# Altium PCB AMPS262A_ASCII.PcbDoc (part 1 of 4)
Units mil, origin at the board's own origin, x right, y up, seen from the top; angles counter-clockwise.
Board outline 5314.96 x 4803.15 mil, 4 copper layers (Top Layer, GND, Copper Layer 3, Bottom Layer), stack 79.28 mil thick; 324 components, 156 nets, 943 pads, 1411 vias.
Unrouted connection lines stored in the file: 130.
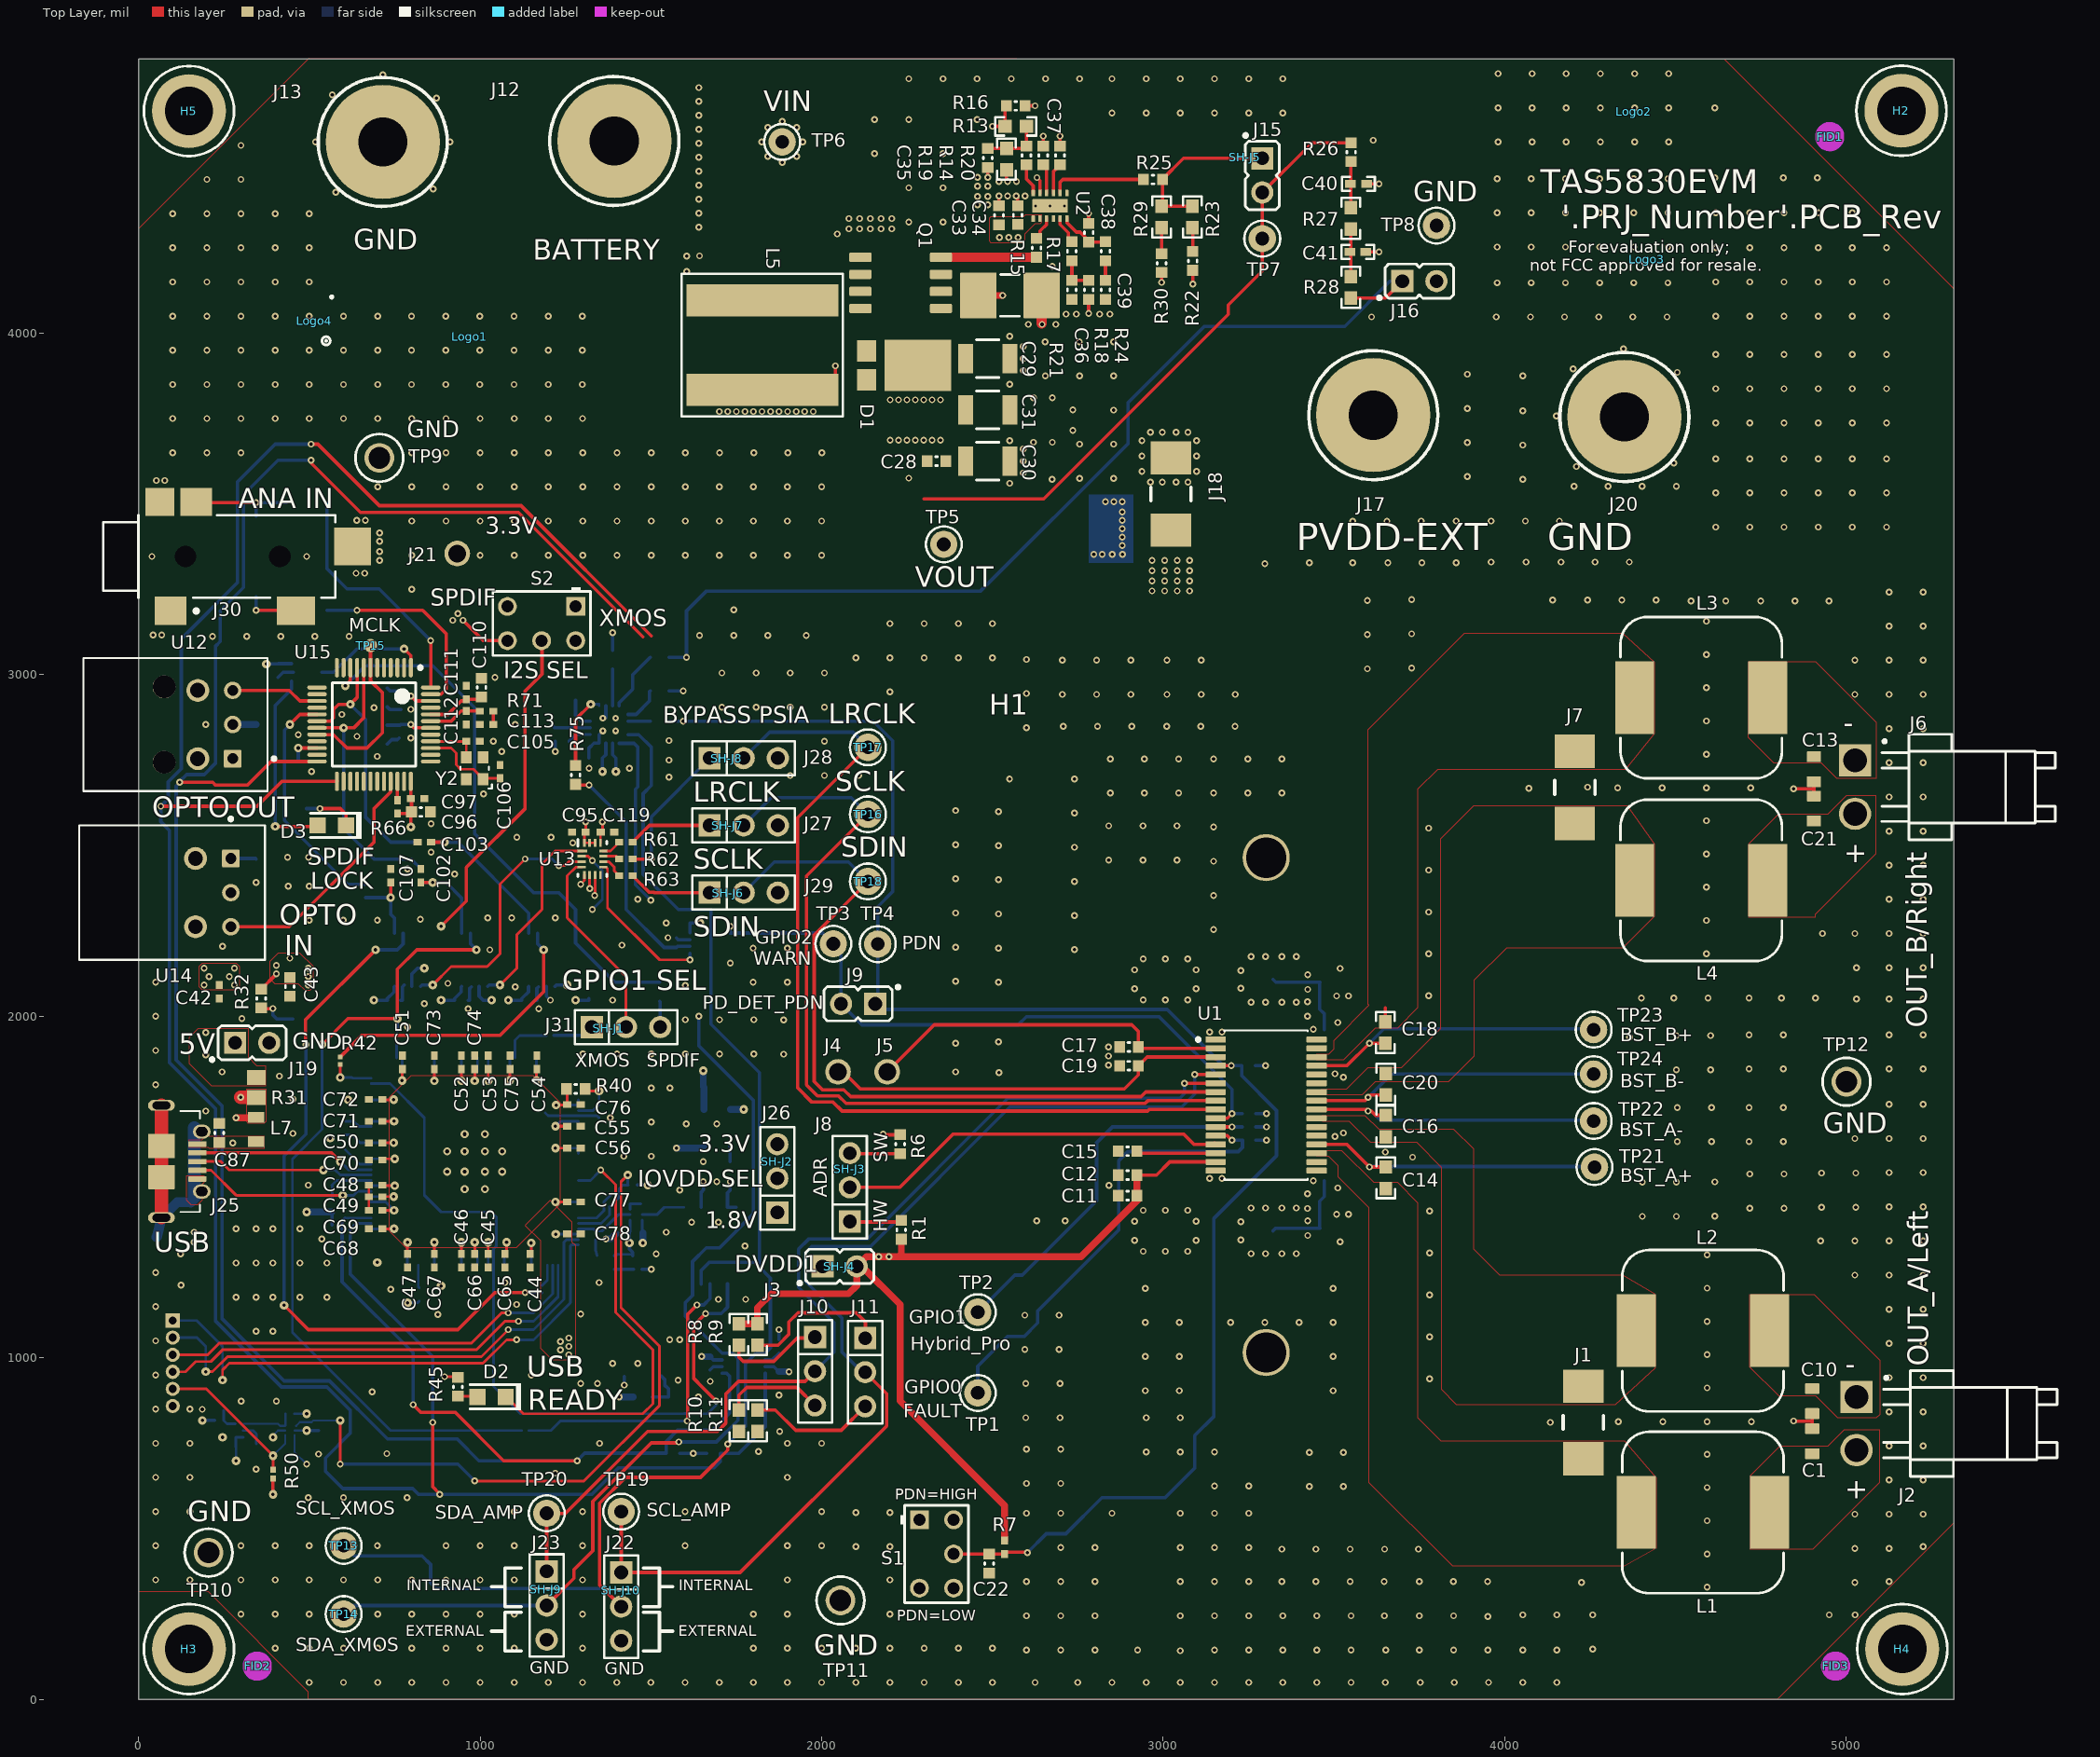
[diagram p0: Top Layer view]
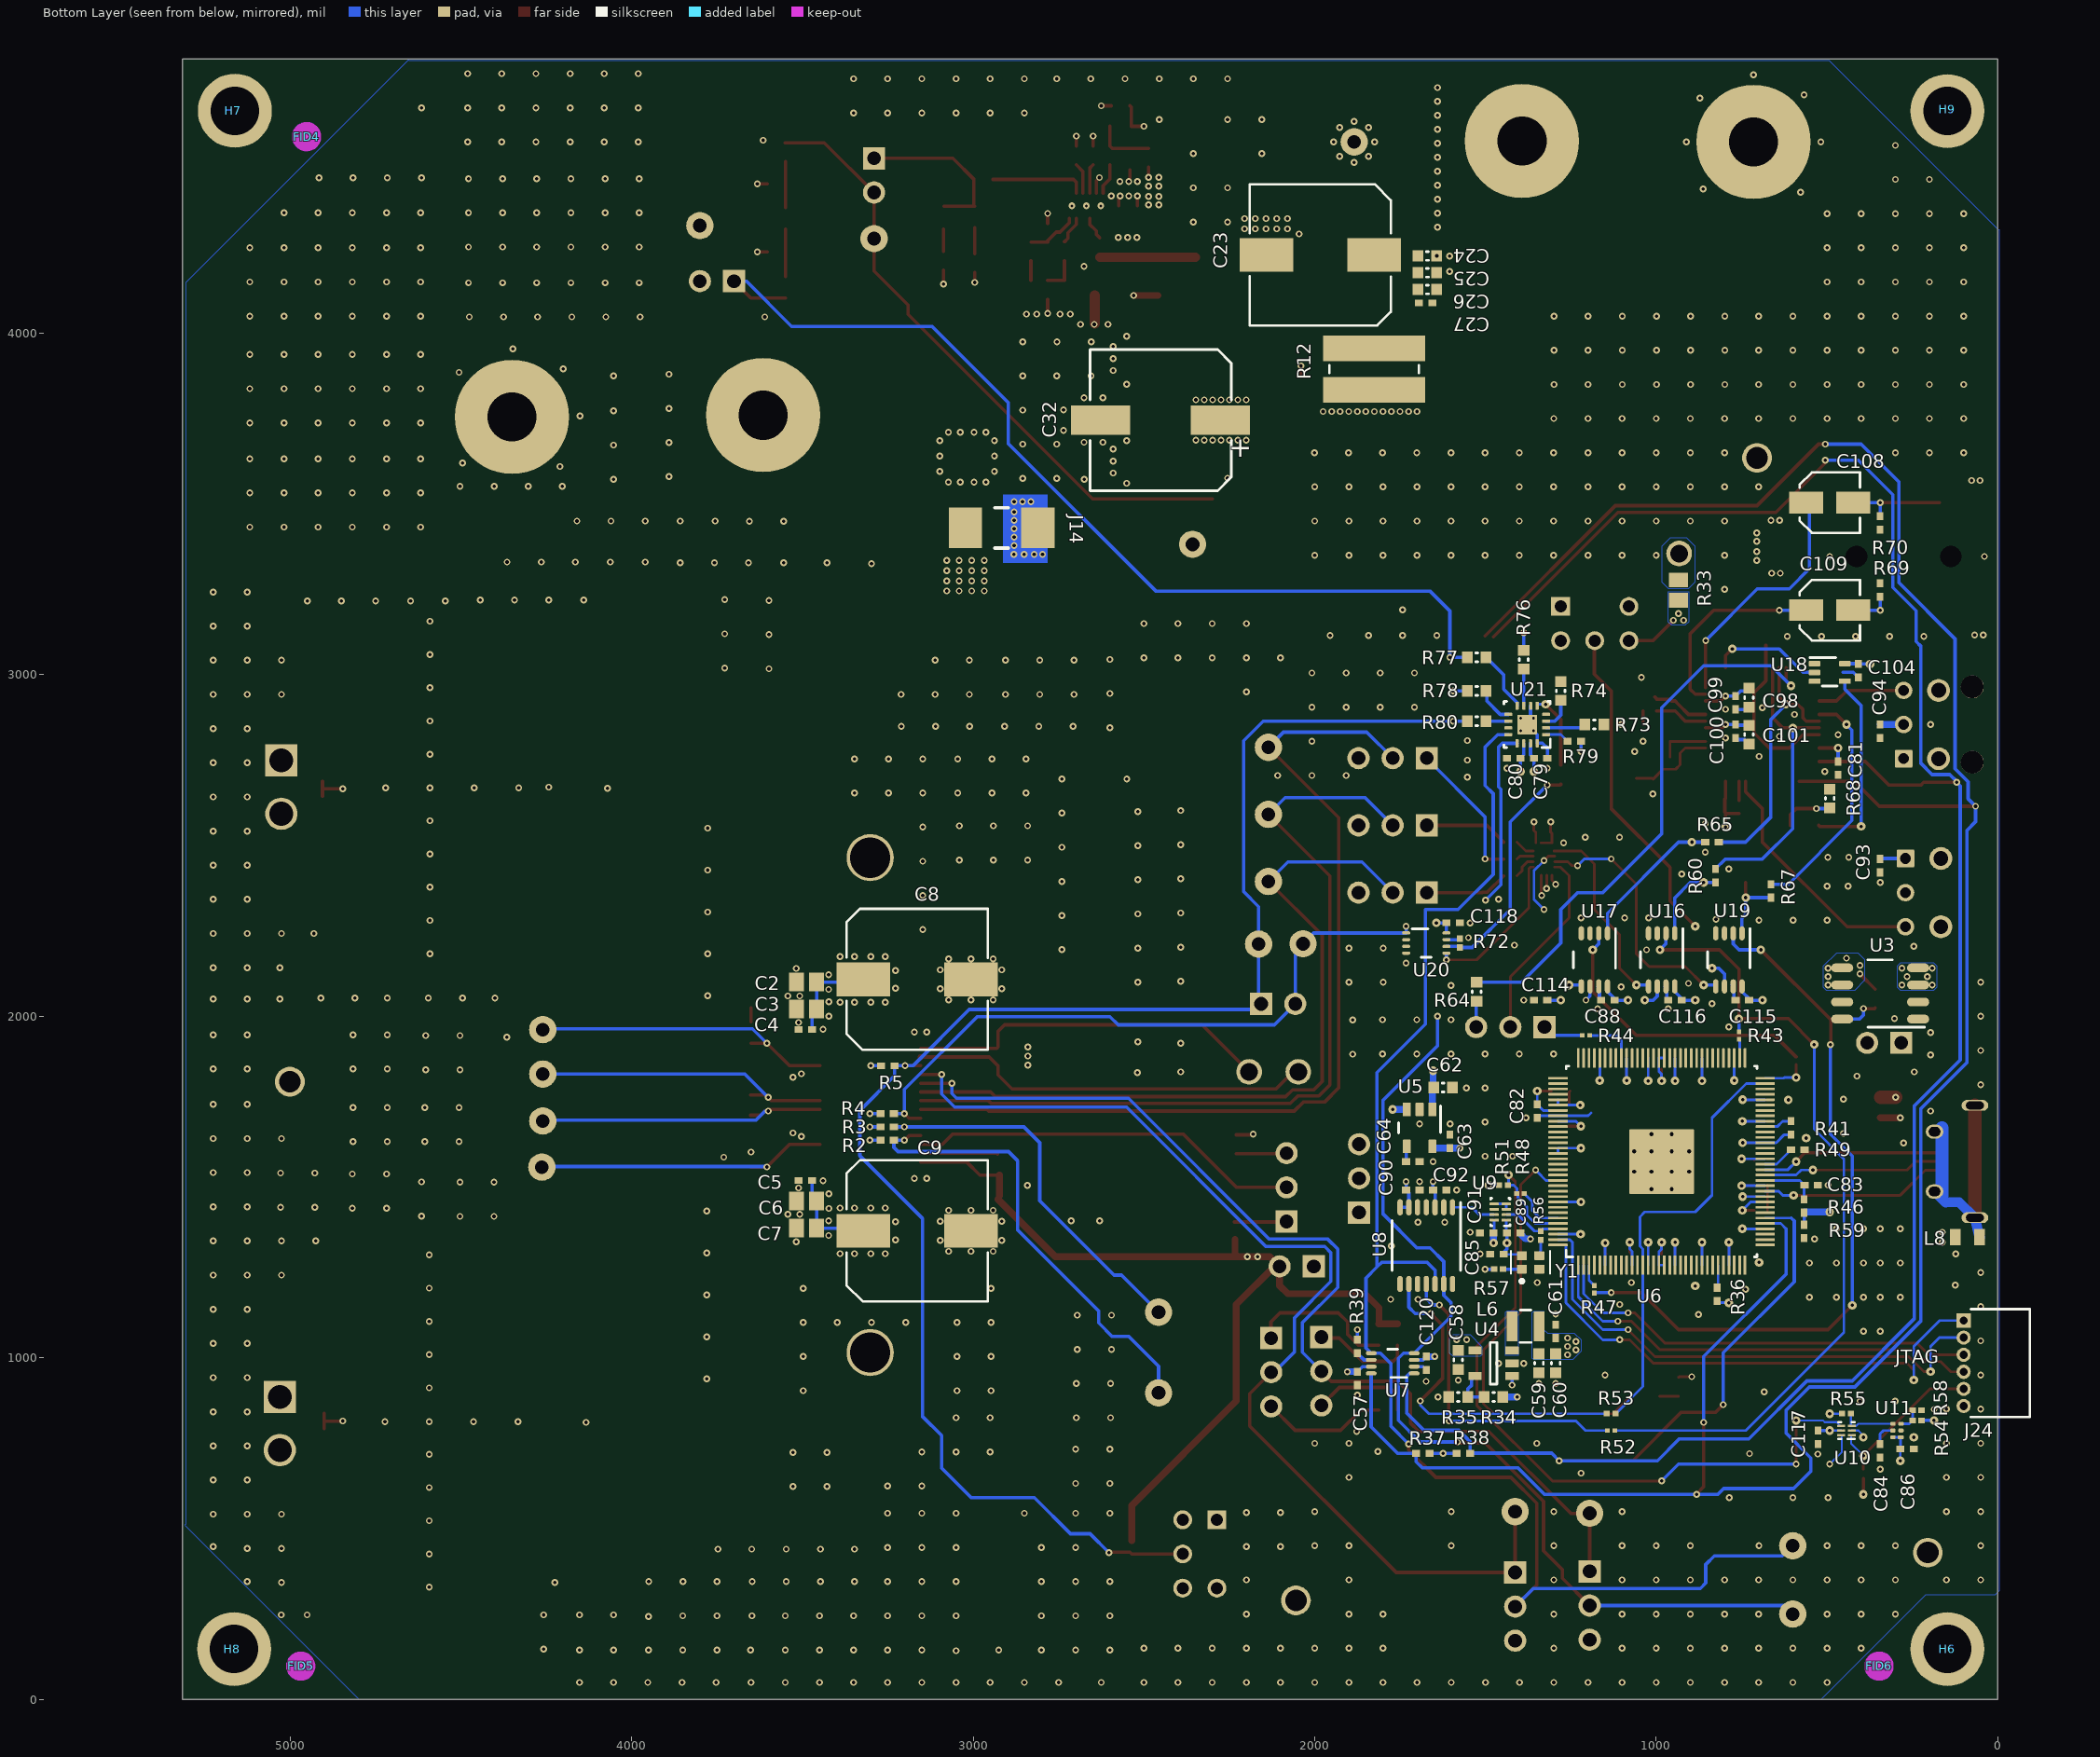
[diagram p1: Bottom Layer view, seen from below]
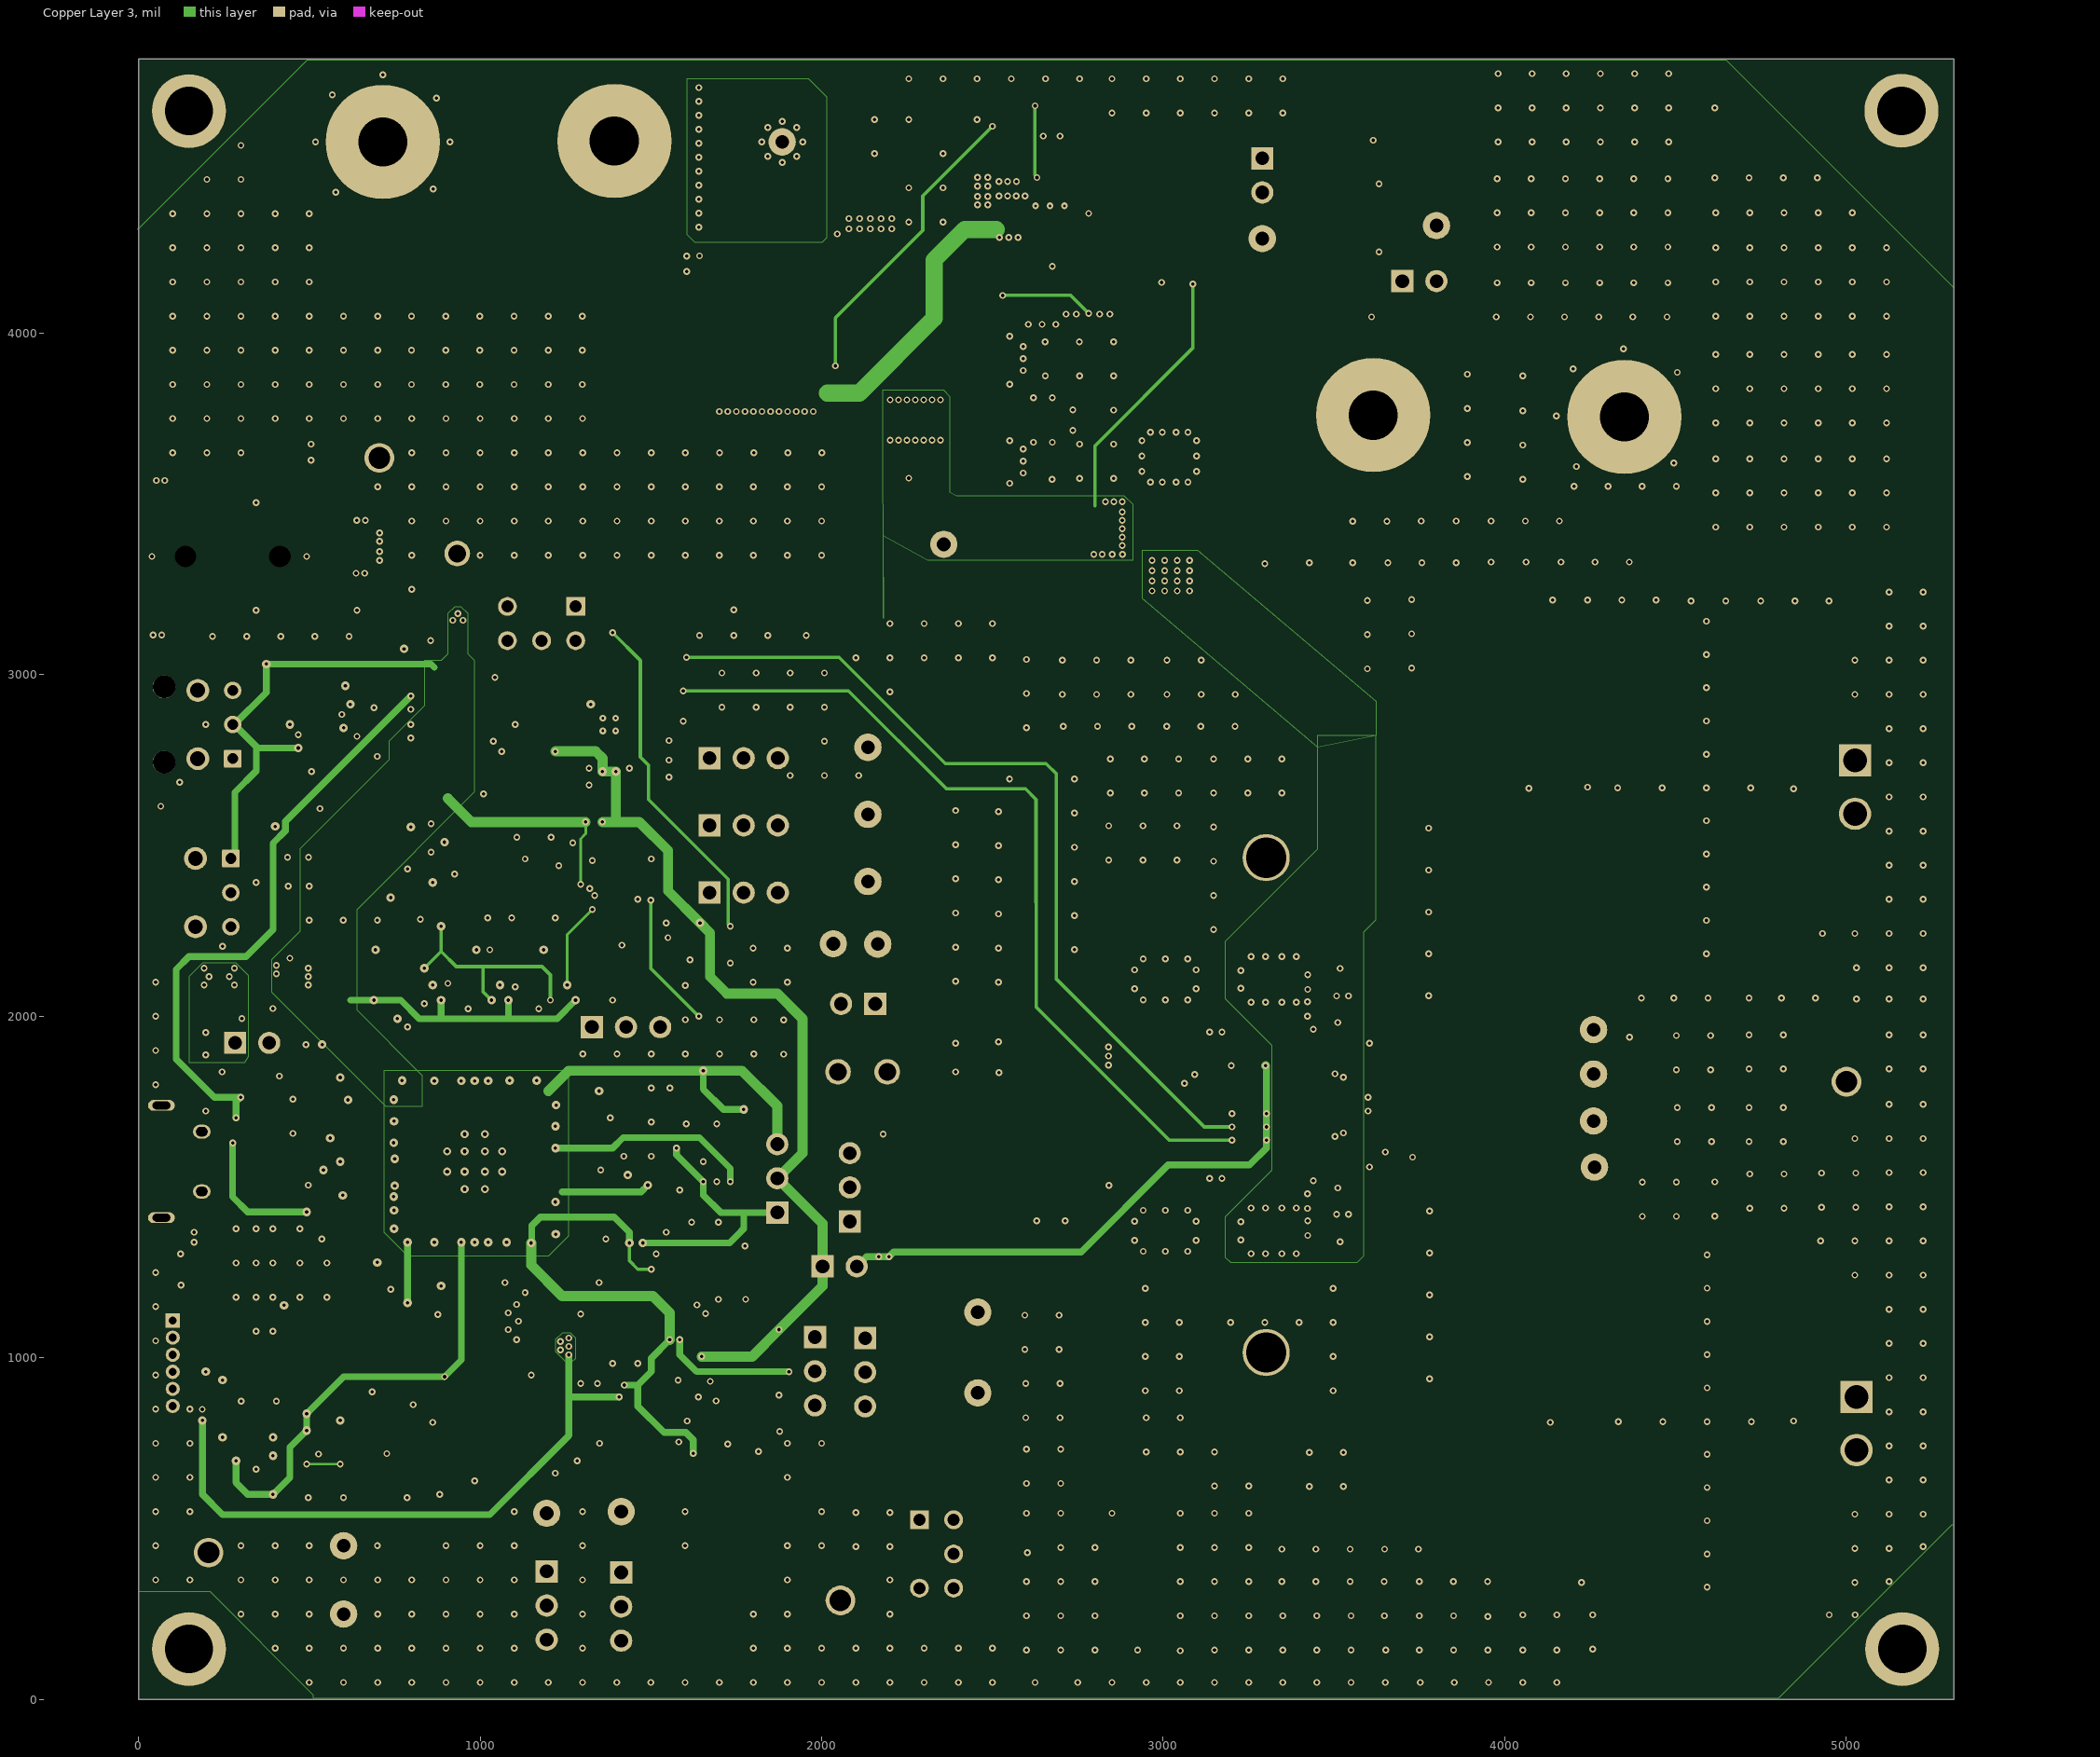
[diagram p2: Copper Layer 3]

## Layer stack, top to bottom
Top Solder: solder mask 0.4, Solder Resist, Dk 3.5
Top Layer: signal copper 2.74
Dielectric 1: prepreg 25, FR-4, Dk 4.2
GND: signal copper 1.4
Dielectric1: core 21, FR-4, Dk 4.2
Copper Layer 3: signal copper 1.4
Dielectric 3: prepreg 25, FR-4, Dk 4.2
Bottom Layer: signal copper 2.74
Bottom Solder: solder mask 0.4, Solder Resist, Dk 3.5

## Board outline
0,0 0,4803.15 5314.96,4803.15 5314.96,0

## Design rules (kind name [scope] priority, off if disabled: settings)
AcuteAngle [All] p0: scope1count=1 scope1_0_kind=Board scope1_0_value=Board scope2count=1 scope2_0_kind=Board scope2_0_value=Board commentlength=0 minimum=4.50000000000000E+0001
AcuteAngle [All] p1: minimum=4.50000000000000E+0001 checktracksonly=FALSE
AssemblyTestPointUsage [All] p0: scope1count=1 scope1_0_kind=Board scope1_0_value=Board scope2count=1 scope2_0_kind=Board scope2_0_value=Board commentlength=0
AssemblyTestPointUsage [All] p1: valid=2
AssemblyTestpoint [All] p0: scope1count=1 scope1_0_kind=Board scope1_0_value=Board scope2count=1 scope2_0_kind=Board scope2_0_value=Board commentlength=0
BoardOutlineClearance [All] p0 off: scope1count=1 scope1_0_kind=Board scope1_0_value=Board scope2count=1 scope2_0_kind=Board scope2_0_value=Board commentlength=172 gap=75 // Protel DXP Scope 1 Expression Was: OnCopper and Not InComponentClass('Logo') and not InComponentClass('FiducialMark') and not InRegion(1000,500,4000,800) and not InPoly
BoardOutlineClearance BoardOutlineClearance_CONN_USB_DX4R205JJA [All] p0 off: scope1count=1 scope1_0_kind=Board scope1_0_value=Board scope2count=1 scope2_0_kind=Board scope2_0_value=Board commentlength=254 gap=75 // Protel DXP Scope 1 Expression Was: (OnCopper AND (HasFootprint('CONN_USB_DX4R205JJA') OR HasFootprint('SWITCHCRAFT_35RASM'))) and Not InComponentClass('Logo') and not InComponentClass('FiducialMark') and not InRegion(1000,500,4000,800) and not InPoly
BoardOutlineClearance BoardOutlineClearance_Poly [All] p0 off: scope1count=1 scope1_0_kind=Board scope1_0_value=Board scope2count=1 scope2_0_kind=Board scope2_0_value=Board commentlength=58 gap=25 // Protel DXP Scope 1 Expression Was: OnCopper and IsPoly
BoardOutlineClearance BoardOutlineClearance_MountingHoles [All] p0 off: scope1count=1 scope1_0_kind=Board scope1_0_value=Board scope2count=1 scope2_0_kind=Board scope2_0_value=Board commentlength=86 gap=39.37 // Protel DXP Scope 1 Expression Was: OnCopper and InComponentClass('Mounting Holes')
BoardOutlineClearance BoardOutlineClearance_MountingHoles [OnCopper and InComponentClass('Mounting Holes')] p1: gap=39.37 ignorepadtopadclearanceinfootprint=FALSE
BoardOutlineClearance BoardOutlineClearance_Poly [OnCopper and IsPoly] p2: gap=25 ignorepadtopadclearanceinfootprint=FALSE
BoardOutlineClearance BoardOutlineClearance_CONN_USB_DX4R205JJA [(OnCopper AND (HasFootprint('CONN_USB_DX4R205JJA') OR HasFootprint('SWITCHCRAFT_35RASM'))) and Not InComponentClass('Logo') and not InComponentClass('FiducialMark') and not InRegion(1000,500,4000,800) and not InPoly] p3: gap=75 ignorepadtopadclearanceinfootprint=FALSE except(15: SMDPad-OutlineEdge THPad-OutlineEdge; 29: Via-OutlineEdge)
BoardOutlineClearance [OnCopper and Not InComponentClass('Logo') and not InComponentClass('FiducialMark') and not InRegion(1000,500,4000,800) and not InPoly] p4: gap=75 ignorepadtopadclearanceinfootprint=FALSE except(20: Track-OutlineEdge; 25: Poly-OutlineEdge Poly-CavityEdge Poly-CutoutEdge Poly-SplitBarrior Poly-SplitContinuation Region-OutlineEdge Region-CavityEdge Region-CutoutEdge Region-SplitBarrior Region-SplitContinuation; 29: Via-OutlineEdge; 35: SMDPad-OutlineEdge; 39.37: THPad-OutlineEdge)
Clearance "FootPrint Lib Error" [All] p0: scope1count=1 scope1_0_kind=Footprint scope1_0_value=DSF* scope2count=1 scope2_0_kind=Board scope2_0_value=Board commentlength=0 gap=7
Clearance [All] p0: scope1count=1 scope1_0_kind=Board scope1_0_value=Board scope2count=1 scope2_0_kind=Board scope2_0_value=Board commentlength=0 gap=7.87
Clearance Clearance_FiducialMark [All] p0 off: scope1count=1 scope1_0_kind=Board scope1_0_value=Board scope2count=1 scope2_0_kind=Board scope2_0_value=Board commentlength=81 gap=0 // Protel DXP Scope 2 Expression Was: IsPad and InComponentClass('FiducialMark')
Clearance Clearance_Poly [All] p0 off: scope1count=1 scope1_0_kind=Board scope1_0_value=Board scope2count=1 scope2_0_kind=Board scope2_0_value=Board commentlength=48 gap=7.87 // Protel DXP Scope 1 Expression Was: InPolygon
Clearance Clearance_Keepouts [All] p0 off: scope1count=1 scope1_0_kind=Board scope1_0_value=Board scope2count=1 scope2_0_kind=Board scope2_0_value=Board commentlength=99 gap=0 // Protel DXP Scope 2 Expression Was: ((IsTrack Or IsArc) And Not InPoly) And IsFree and IsKeepOut
Clearance Clearance_FiducialMark [IsKeepOut and InComponentClass('FiducialMark') vs IsPad and InComponentClass('FiducialMark')] p1: gap=0 ignorepadtopadclearanceinfootprint=FALSE
Clearance Clearance_Keepouts [((IsTrack Or IsArc) And Not InPoly) And IsFree and IsKeepOut vs ((IsTrack Or IsArc) And Not InPoly) And IsFree and IsKeepOut] p2: gap=0 ignorepadtopadclearanceinfootprint=FALSE
Clearance Clearance_Poly [InPolygon] p3: gap=7.87 ignorepadtopadclearanceinfootprint=TRUE
Clearance "FootPrint Lib Error" [HasFootprint('DSF*')] p4: gap=7 ignorepadtopadclearanceinfootprint=TRUE except(0: Arc-Hole Track-Hole SMDPad-Hole THPad-Hole Via-Hole Fill-Hole Poly-Hole Region-Hole Text-Hole)
Clearance [All] p5: gap=7.87 ignorepadtopadclearanceinfootprint=TRUE except(0: Arc-Hole Track-Hole SMDPad-Hole THPad-Hole Via-Hole Fill-Hole Poly-Hole Region-Hole Text-Hole)
ComponentClearance ComponentClearance_MOUNTINGHOLE [All] p0 off: scope1count=1 scope1_0_kind=Footprint scope1_0_value="APM_RM3X8MM 2701" scope2count=1 scope2_0_kind=Footprint scope2_0_value=Keystone_24434 commentlength=0 gap=0 collisioncheckmode=3
ComponentClearance ComponentClearance_HEATSINK [All] p0 off: scope1count=1 scope1_0_kind=Component scope1_0_value=H1 scope2count=1 scope2_0_kind=Component scope2_0_value=U1 commentlength=0 gap=0 collisioncheckmode=3
ComponentClearance [All] p0 off: scope1count=1 scope1_0_kind=Board scope1_0_value=Board scope2count=1 scope2_0_kind=Board scope2_0_value=Board commentlength=0 gap=0 collisioncheckmode=3
ComponentClearance ComponentClearance_THtoTH [All] p0 off: scope1count=1 scope1_0_kind=Board scope1_0_value=Board scope2count=1 scope2_0_kind=Board scope2_0_value=Board commentlength=54 gap=30 collisioncheckmode=3 // Protel DXP Scope 2 Expression Was: IsThruComponent
ComponentClearance ComponentClearance_THtoSMT [All] p0 off: scope1count=1 scope1_0_kind=Board scope1_0_value=Board scope2count=1 scope2_0_kind=Board scope2_0_value=Board commentlength=53 gap=25 collisioncheckmode=3 // Protel DXP Scope 2 Expression Was: IsSMTComponent
ComponentClearance ComponentClearance_SmallPassives [All] p0 off: scope1count=1 scope1_0_kind=Board scope1_0_value=Board scope2count=1 scope2_0_kind=Board scope2_0_value=Board commentlength=1054 gap=8.5 collisioncheckmode=3 // Protel DXP Scope 2 Expression Was: HasFootprint('0201*') or HasFootprint('0402*') or HasFootprint('0603*') or HasFootprint('0805*') or HasFootprint('1206*') or HasFootprint('1210*') or HasFootprint('1008*') or HasFootprint('2512*') or HasFootprint('Abracon*') or HasFootprint('DBV*') or HasFootprint('DC*') or HasFootprint('DDA*') or HasFootprint('DEM*') or HasFootprint('DFE*') or HasFootprint('DQM*') or HasFootprint('DRL*') or HasFootprint('DRY*') or HasFootprint('DSF*') or HasFootprint('DSS*') or HasFootprint('FDSD*') or HasFootprint('HAR*') or HasFootprint('HXB*') or HasFootprint('IND*') or HasFootprint('LDC*') or HasFootprint('LTST*') or HasFootprint('MPZ*') or HasFootprint('MRA*') or HasFootprint('NFZ*') or HasFootprint('PG*') or HasFootprint('PW*') or HasFootprint('PT*') or HasFootprint('Relay*') or HasFootprint('RGT*') or HasFootprint('RHB*') or HasFootprint('RLT*') or HasFootprint('RSV*') or HasFootprint('SM*') or HasFootprint('SOT*') or HasFootprint('TP*') or HasFootprint('VLS*') or HasFootprint('XAL*') or HasFootprint('XTAL*')
ComponentClearance ComponentClearance_MountingHoles [All] p0 off: scope1count=1 scope1_0_kind=ComponentClass scope1_0_value="Mounting Holes" scope2count=1 scope2_0_kind=Board scope2_0_value=Board commentlength=0 gap=250 collisioncheckmode=3
ComponentClearance ComponentClearance_ScrewToNut [All] p0 off: scope1count=1 scope1_0_kind=Board scope1_0_value=Board scope2count=1 scope2_0_kind=Board scope2_0_value=Board commentlength=71 gap=5 collisioncheckmode=3 // Protel DXP Scope 2 Expression Was: (HasFootprint('Keystone_1902C'))
ComponentClearance ComponentClearance_Logo [All] p0 off: scope1count=1 scope1_0_kind=ComponentClass scope1_0_value=Logo scope2count=1 scope2_0_kind=Board scope2_0_value=Board commentlength=0 gap=50 collisioncheckmode=3
ComponentClearance ComponentClearance_Shunt [All] p0 off: scope1count=1 scope1_0_kind=ComponentClass scope1_0_value=Header scope2count=1 scope2_0_kind=ComponentClass scope2_0_value=Shunt commentlength=0 gap=0 collisioncheckmode=3
ComponentClearance ComponentClearance_MountingHoles_FiducialMarks [All] p0 off: scope1count=1 scope1_0_kind=ComponentClass scope1_0_value="Mounting Holes" scope2count=1 scope2_0_kind=ComponentClass scope2_0_value=FiducialMark commentlength=0 gap=50 collisioncheckmode=3
ComponentClearance ComponentClearance_MOUNTINGHOLE [HasFootprint('APM_RM3X8MM 2701') vs HasFootprint('Keystone_24434')] p1 off: gap=0 collisioncheckmode=3 verticalgap=0 showdistances=FALSE
ComponentClearance ComponentClearance_HEATSINK [InComponent('H1') vs InComponent('U1')] p2 off: gap=0 collisioncheckmode=3 verticalgap=0 showdistances=FALSE
ComponentClearance ComponentClearance_MountingHoles_FiducialMarks [InComponentClass('Mounting Holes') vs InComponentClass('FiducialMark')] p3 off: gap=50 collisioncheckmode=3 verticalgap=10 showdistances=FALSE
ComponentClearance ComponentClearance_Shunt [InComponentClass('Header') vs InComponentClass('Shunt')] p4 off: gap=0 collisioncheckmode=3 verticalgap=0 showdistances=FALSE
ComponentClearance ComponentClearance_Logo [InComponentClass('Logo')] p5 off: gap=50 collisioncheckmode=3 verticalgap=10 showdistances=FALSE
ComponentClearance ComponentClearance_ScrewToNut [(HasFootprint('NY PMS 440 0025 PH')) vs (HasFootprint('Keystone_1902C'))] p6 off: gap=5 collisioncheckmode=3 verticalgap=10 showdistances=FALSE
ComponentClearance ComponentClearance_MountingHoles [InComponentClass('Mounting Holes')] p7 off: gap=250 collisioncheckmode=3 verticalgap=100000 showdistances=FALSE
ComponentClearance ComponentClearance_SmallPassives [HasFootprint('0201*') or HasFootprint('0402*') or HasFootprint('0603*') or HasFootprint('0805*') or HasFootprint('1206*') or HasFootprint('1210*') or HasFootprint('1008*') or HasFootprint('2512*') or HasFootprint('Abracon*') or HasFootprint('DBV*') or HasFootprint('DC*') or HasFootprint('DDA*') or HasFootprint('DEM*') or HasFootprint('DFE*') or HasFootprint('DQM*') or HasFootprint('DRL*') or HasFootprint('DRY*') or HasFootprint('DSF*') or HasFootprint('DSS*') or HasFootprint('FDSD*') or HasFootprint('HAR*') or HasFootprint('HXB*') or HasFootprint('IND*') or HasFootprint('LDC*') or HasFootprint('LTST*') or HasFootprint('MPZ*') or HasFootprint('MRA*') or HasFootprint('NFZ*') or HasFootprint('PG*') or HasFootprint('PW*') or HasFootprint('PT*') or HasFootprint('Relay*') or HasFootprint('RGT*') or HasFootprint('RHB*') or HasFootprint('RLT*') or HasFootprint('RSV*') or HasFootprint('SM*') or HasFootprint('SOT*') or HasFootprint('TP*') or HasFootprint('VLS*') or HasFootprint('XAL*') or HasFootprint('XTAL*') vs HasFootprint('0201*') or HasFootprint('0402*') or HasFootprint('0603*') or HasFootprint('0805*') or HasFootprint('1206*') or HasFootprint('1210*') or HasFootprint('1008*') or HasFootprint('2512*') or HasFootprint('Abracon*') or HasFootprint('DBV*') or HasFootprint('DC*') or HasFootprint('DDA*') or HasFootprint('DEM*') or HasFootprint('DFE*') or HasFootprint('DQM*') or HasFootprint('DRL*') or HasFootprint('DRY*') or HasFootprint('DSF*') or HasFootprint('DSS*') or HasFootprint('FDSD*') or HasFootprint('HAR*') or HasFootprint('HXB*') or HasFootprint('IND*') or HasFootprint('LDC*') or HasFootprint('LTST*') or HasFootprint('MPZ*') or HasFootprint('MRA*') or HasFootprint('NFZ*') or HasFootprint('PG*') or HasFootprint('PW*') or HasFootprint('PT*') or HasFootprint('Relay*') or HasFootprint('RGT*') or HasFootprint('RHB*') or HasFootprint('RLT*') or HasFootprint('RSV*') or HasFootprint('SM*') or HasFootprint('SOT*') or HasFootprint('TP*') or HasFootprint('VLS*') or HasFootprint('XAL*') or HasFootprint('XTAL*')] p8 off: gap=8.5 collisioncheckmode=3 verticalgap=10 showdistances=FALSE
ComponentClearance ComponentClearance_THtoSMT [IsThruComponent vs IsSMTComponent] p9 off: gap=25 collisioncheckmode=3 verticalgap=30 showdistances=FALSE
ComponentClearance ComponentClearance_THtoTH [IsThruComponent vs IsThruComponent] p10 off: gap=30 collisioncheckmode=3 verticalgap=30 showdistances=FALSE
ComponentClearance [All] p11 off: gap=0 collisioncheckmode=3 verticalgap=10 showdistances=FALSE
DiffPairsRouting [All] p0: scope1count=1 scope1_0_kind=Board scope1_0_value=Board scope2count=1 scope2_0_kind=Board scope2_0_value=Board commentlength=0
DiffPairsRouting [All] p1: maxlimit=100 minlimit=10 mostfreqgap=10 toplayer_minwidth=15 toplayer_maxwidth=15 toplayer_prefwidth=15 midlayer1_minwidth=15 midlayer1_maxwidth=15 midlayer1_prefwidth=15 midlayer2_minwidth=15 midlayer2_maxwidth=15 midlayer2_prefwidth=15 bottomlayer_minwidth=15 bottomlayer_maxwidth=15 bottomlayer_prefwidth=15 maxuncoupledlength=1000
FabricationTestPointUsage TestPointUsage [All] p0: scope1count=1 scope1_0_kind=Board scope1_0_value=Board scope2count=1 scope2_0_kind=Board scope2_0_value=Board commentlength=0 valid=2 allowmultiple=FALSE
FabricationTestPointUsage TestPointUsage [All] p1: valid=2 allowmultiple=FALSE
FabricationTestpoint Testpoint [All] p0: scope1count=1 scope1_0_kind=Board scope1_0_value=Board scope2count=1 scope2_0_kind=Board scope2_0_value=Board commentlength=0 side=3 testpointundercomponent=TRUE minsize=40 maxsize=100 preferedsize=60 minholesize=0 maxholesize=40 preferedholesize=32 testpointgrid=1
FabricationTestpoint Testpoint [All] p1: side=3 testpointundercomponent=TRUE minsize=40 maxsize=100 preferedsize=60 minholesize=0 maxholesize=40 preferedholesize=32 testpointgrid=1 allowsidetop=TRUE allowsidebottom=TRUE usegrid=TRUE gridtolerance=0.01
FanoutControl Fanout_Small [All] p0 off: scope1count=1 scope1_0_kind=Board scope1_0_value=Board scope2count=1 scope2_0_kind=Board scope2_0_value=Board commentlength=84 // Protel DXP Scope 1 Expression Was: (CompPinCount < 5)   Fanout_Small (Default Rule)
FanoutControl Fanout_Default [All] p0: scope1count=1 scope1_0_kind=Board scope1_0_value=Board scope2count=1 scope2_0_kind=Board scope2_0_value=Board commentlength=30 // Fanout_Default (Default Rule)
FanoutControl Fanout_SOIC [All] p0 off: scope1count=1 scope1_0_kind=Board scope1_0_value=Board scope2count=1 scope2_0_kind=Board scope2_0_value=Board commentlength=71 // Protel DXP Scope 1 Expression Was: IsSOIC   Fanout_SOIC (Default Rule)
FanoutControl Fanout_BGA [All] p0 off: scope1count=1 scope1_0_kind=Board scope1_0_value=Board scope2count=1 scope2_0_kind=Board scope2_0_value=Board commentlength=69 // Protel DXP Scope 1 Expression Was: IsBGA   Fanout_BGA (Default Rule)
FanoutControl Fanout_LCC [All] p0 off: scope1count=1 scope1_0_kind=Board scope1_0_value=Board scope2count=1 scope2_0_kind=Board scope2_0_value=Board commentlength=69 // Protel DXP Scope 1 Expression Was: IsLCC   Fanout_LCC (Default Rule)
FanoutControl Fanout_LCC [IsLCC] p1: bgadir=Out bgaviamode=Centered fanoutstyle=Auto fanoutdirection=Alternating viagrid=1 // Fanout_LCC (Default Rule)
FanoutControl Fanout_BGA [IsBGA] p2: bgadir=Out bgaviamode=Centered fanoutstyle=Auto fanoutdirection=Alternating viagrid=1 // Fanout_BGA (Default Rule)
FanoutControl Fanout_Default [All] p4: bgadir=Out bgaviamode=Centered fanoutstyle=Auto fanoutdirection=Alternating viagrid=1 // Fanout_Default (Default Rule)
FanoutControl Fanout_Small [(CompPinCount < 5)] p5: bgadir=Out bgaviamode=Centered fanoutstyle=Auto fanoutdirection=OutThenIn viagrid=1 // Fanout_Small (Default Rule)
Height [All] p0 off: scope1count=1 scope1_0_kind=Board scope1_0_value=Board scope2count=1 scope2_0_kind=Board scope2_0_value=Board commentlength=0
Height [All] p1 off: minheight=0 maxheight=1050 prefheight=500
HoleSize [All] p0: scope1count=1 scope1_0_kind=Board scope1_0_value=Board scope2count=1 scope2_0_kind=Board scope2_0_value=Board commentlength=0 absolutevalues=TRUE maxlimit=251 minlimit=7.87 maxpercent=80.000 minpercent=20.000
HoleSize [All] p1: absolutevalues=TRUE maxlimit=251 minlimit=7.87 maxpercent=80.000 minpercent=20.000
HoleToHoleClearance [All] p0: scope1count=1 scope1_0_kind=Board scope1_0_value=Board scope2count=1 scope2_0_kind=Board scope2_0_value=Board commentlength=0
LayerPairs [All] p0: scope1count=1 scope1_0_kind=Board scope1_0_value=Board scope2count=1 scope2_0_kind=Board scope2_0_value=Board commentlength=0 enforce=TRUE
MinimumAnnularRing [All] p0: scope1count=1 scope1_0_kind=Board scope1_0_value=Board scope2count=1 scope2_0_kind=Board scope2_0_value=Board commentlength=0 minimumring=5
MinimumAnnularRing MinimumAnnularRing_ThermalPadVias [All] p0 off: scope1count=1 scope1_0_kind=Board scope1_0_value=Board scope2count=1 scope2_0_kind=Board scope2_0_value=Board commentlength=63 minimumring=5.91 // Protel DXP Scope 1 Expression Was: IsVia and InAnyComponent
MinimumAnnularRing MinimumAnnularRing_ThermalPadVias [IsVia and InAnyComponent] p1: minimumring=5.91
MinimumAnnularRing [All] p2: minimumring=5
MinimumSolderMaskSliver MinimumSolderMaskSliver_DSF [All] p0: scope1count=1 scope1_0_kind=Footprint scope1_0_value=DSF* scope2count=1 scope2_0_kind=Board scope2_0_value=Board commentlength=0
MinimumSolderMaskSliver [All] p0: scope1count=1 scope1_0_kind=Board scope1_0_value=Board scope2count=1 scope2_0_kind=Board scope2_0_value=Board commentlength=0
MinimumSolderMaskSliver MinimumSolderMaskSliver_Logo [All] p0: scope1count=1 scope1_0_kind=ComponentClass scope1_0_value=Logo scope2count=1 scope2_0_kind=ComponentClass scope2_0_value=Logo commentlength=0
MinimumSolderMaskSliver MinimumSolderMaskSliver_Logo [InComponentClass('Logo') vs InComponentClass('Logo')] p1: minsoldermaskwidth=0.7
MinimumSolderMaskSliver MinimumSolderMaskSliver_DSF [HasFootprint('DSF*')] p2: minsoldermaskwidth=3.5
MinimumSolderMaskSliver [All] p3: minsoldermaskwidth=3.94
NetAntennae [All] p0: scope1count=1 scope1_0_kind=Net scope1_0_value="No Net" scope2count=1 scope2_0_kind=Board scope2_0_value=Board commentlength=0
NetAntennae [InNet('No Net')] p1: netantennaetolerance=0
PasteMaskExpansion [All] p0: scope1count=1 scope1_0_kind=Board scope1_0_value=Board scope2count=1 scope2_0_kind=Board scope2_0_value=Board commentlength=0 expansion=0
PlaneClearance [All] p0: scope1count=1 scope1_0_kind=Board scope1_0_value=Board scope2count=1 scope2_0_kind=Board scope2_0_value=Board commentlength=0 clearance=20
PlaneConnect [All] p0: scope1count=1 scope1_0_kind=Board scope1_0_value=Board scope2count=1 scope2_0_kind=Board scope2_0_value=Board commentlength=0 planeconnectstyle=Relief reliefexpansion=10 reliefentries=4 reliefconductorwidth=10 reliefairgap=10
PlaneConnect [All] p1: planeconnectstyle=Relief reliefexpansion=10 reliefentries=4 reliefconductorwidth=10 reliefairgap=10
PolygonConnect "Pre Flood" [All] p0: scope1count=1 scope1_0_kind=Board scope1_0_value=Board scope2count=1 scope2_0_kind=Board scope2_0_value=Board commentlength=0 connectstyle=Direct reliefconductorwidth=10 reliefentries=4 polygonreliefangle="90 Angle"
PolygonConnect "GND Thermals 0.25mm" [All] p0 off: scope1count=1 scope1_0_kind=Board scope1_0_value=Board scope2count=1 scope2_0_kind=Net scope2_0_value=GND commentlength=209 connectstyle=Relief reliefconductorwidth=9.84 reliefentries=4 polygonreliefangle="90 Angle" // Protel DXP Scope 1 Expression Was: InComponent('C*') or InComponent('J*') or InComponent('L*') or  InComponent('R*') or InComponent('S*') or InComponent('TP*') or  InComponent('Y*') or  InComponent('GND*')
PolygonConnect "PVDD Thermals 0.75mm" [All] p0: scope1count=1 scope1_0_kind=ComponentClass scope1_0_value="GND Thermals 0.75mm" scope2count=1 scope2_0_kind=Net scope2_0_value=GND commentlength=0 connectstyle=Relief reliefconductorwidth=29.53 reliefentries=4 polygonreliefangle="90 Angle"
PolygonConnect "GND Thermals 0.5mm" [All] p0: scope1count=1 scope1_0_kind=ComponentClass scope1_0_value="GND Thermals 0.5mm" scope2count=1 scope2_0_kind=Net scope2_0_value=GND commentlength=0 connectstyle=Relief reliefconductorwidth=19.68 reliefentries=4 polygonreliefangle="90 Angle"
PolygonConnect "Post Flood GND" [All] p0 off: scope1count=1 scope1_0_kind=Board scope1_0_value=Board scope2count=1 scope2_0_kind=Net scope2_0_value=GND commentlength=314 connectstyle=Direct reliefconductorwidth=10 reliefentries=4 polygonreliefangle="90 Angle" // Protel DXP Scope 1 Expression Was: (HasFootprint('DKQ*') or HasFootprint('LDC*') or HasFootprint('MRA*') or HasFootprint('PW*') or HasFootprint('RHB*') or HasFootprint('RLT*') or HasFootprint('TQFP-128')) or InComponentClass('GND Thermals Full Flood') or InComponent('U*') or InComponentClass('GND Full Flood')
PolygonConnect "Flood Copper Planes" [All] p0 off: scope1count=1 scope1_0_kind=Board scope1_0_value=Board scope2count=1 scope2_0_kind=Board scope2_0_value=Board commentlength=210 connectstyle=Direct reliefconductorwidth=10 reliefentries=4 polygonreliefangle="90 Angle" // Protel DXP Scope 1 Expression Was: InNet('1.0V') or InNet('3.3V') or InNet('GND-PS') or InNet('PVDD') or  InNet('PVDD-VR') or  InNet('VIN') or InNet('3.3V-VR') or  InNet('VIN_3.3V-VR') or InNet('PVDD-3.3V')
PolygonConnect "Flood VR Bottom Copper Only" [All] p0: scope1count=1 scope1_0_kind=Net scope1_0_value=GND scope2count=2 scope2_0_kind=Footprint scope2_0_value=DDA0008H_N scope2_1_kind=Layer scope2_1_value=TOP commentlength=0 connectstyle=Direct reliefconductorwidth=10 reliefentries=4 polygonreliefangle="90 Angle"
PolygonConnect "Flood VR Bottom Copper Only" [InNet('GND') vs HasFootprint('DDA0008H_N') And OnLayer('Bottom Copper')] p1: connectstyle=Direct reliefconductorwidth=10 reliefentries=4 polygonreliefangle="90 Angle" airgapwidth=10
PolygonConnect "Flood Copper Planes" [InNet('1.0V') or InNet('3.3V') or InNet('GND-PS') or InNet('PVDD') or  InNet('PVDD-VR') or  InNet('VIN') or InNet('3.3V-VR') or  InNet('VIN_3.3V-VR') or InNet('PVDD-3.3V')] p2: connectstyle=Direct reliefconductorwidth=10 reliefentries=4 polygonreliefangle="90 Angle" airgapwidth=10
PolygonConnect "Post Flood GND" [(HasFootprint('DKQ*') or HasFootprint('LDC*') or HasFootprint('MRA*') or HasFootprint('PW*') or HasFootprint('RHB*') or HasFootprint('RLT*') or HasFootprint('TQFP-128')) or InComponentClass('GND Thermals Full Flood') or InComponent('U*') or InComponentClass('GND Full Flood') vs InNet('GND')] p3: connectstyle=Direct reliefconductorwidth=10 reliefentries=4 polygonreliefangle="90 Angle" airgapwidth=10
PolygonConnect "GND Thermals 0.5mm" [InComponentClass('GND Thermals 0.5mm') vs InNet('GND')] p4: connectstyle=Relief reliefconductorwidth=19.68 reliefentries=4 polygonreliefangle="90 Angle" airgapwidth=9.84
PolygonConnect "PVDD Thermals 0.75mm" [InComponentClass('GND Thermals 0.75mm') vs InNet('GND')] p5: connectstyle=Relief reliefconductorwidth=29.53 reliefentries=4 polygonreliefangle="90 Angle" airgapwidth=9.84
PolygonConnect "GND Thermals 0.25mm" [InComponent('C*') or InComponent('J*') or InComponent('L*') or  InComponent('R*') or InComponent('S*') or InComponent('TP*') or  InComponent('Y*') or  InComponent('GND*') vs InNet('GND')] p6: connectstyle=Relief reliefconductorwidth=9.84 reliefentries=4 polygonreliefangle="90 Angle" airgapwidth=7.87
PolygonConnect "Pre Flood" [All] p7: connectstyle=Direct reliefconductorwidth=10 reliefentries=4 polygonreliefangle="90 Angle" airgapwidth=10
RoutingCorners [All] p0: scope1count=1 scope1_0_kind=Board scope1_0_value=Board scope2count=1 scope2_0_kind=Board scope2_0_value=Board commentlength=0 cornerstyle=45-Degree minsetback=100 maxsetback=100
RoutingLayers [All] p0: scope1count=1 scope1_0_kind=Board scope1_0_value=Board scope2count=1 scope2_0_kind=Board scope2_0_value=Board commentlength=0 top layer=Automatic mid layer 1=Automatic mid layer 2=Automatic bottom layer=Automatic
RoutingPriority [All] p0: scope1count=1 scope1_0_kind=Board scope1_0_value=Board scope2count=1 scope2_0_kind=Board scope2_0_value=Board commentlength=0
RoutingTopology [All] p0: scope1count=1 scope1_0_kind=Board scope1_0_value=Board scope2count=1 scope2_0_kind=Board scope2_0_value=Board commentlength=0 topology=Shortest
RoutingVias [All] p0: scope1count=1 scope1_0_kind=Board scope1_0_value=Board scope2count=1 scope2_0_kind=Board scope2_0_value=Board commentlength=0 holewidth=10 width=20 viastyle="Through Hole" minholewidth=7.87 minwidth=20 maxholewidth=40 maxwidth=65
RoutingVias ThermalPadVias [All] p0 off: scope1count=1 scope1_0_kind=Board scope1_0_value=Board scope2count=1 scope2_0_kind=Board scope2_0_value=Board commentlength=63 holewidth=7.87 width=19.68 viastyle="Through Hole" minholewidth=7.87 minwidth=19.68 maxholewidth=12.99 maxwidth=23.62 // Protel DXP Scope 1 Expression Was: IsVia and InAnyComponent
RoutingVias ThermalPadVias [IsVia and InAnyComponent] p1: holewidth=7.87 width=19.68 viastyle="Through Hole" minholewidth=7.87 minwidth=19.68 maxholewidth=12.99 maxwidth=23.62
RoutingVias [All] p2: holewidth=10 width=20 viastyle="Through Hole" minholewidth=7.87 minwidth=20 maxholewidth=40 maxwidth=65
ShortCircuit [All] p0: scope1count=1 scope1_0_kind=Board scope1_0_value=Board scope2count=1 scope2_0_kind=Board scope2_0_value=Board commentlength=0 allowed=FALSE
SilkToBoardRegionClearance [All] p0 off: scope1count=1 scope1_0_kind=Board scope1_0_value=Board scope2count=1 scope2_0_kind=Board scope2_0_value=Board commentlength=130 // Protel DXP Scope 1 Expression Was: Not ((IsComment or IsDesignator) And (Hide <> 'False')) and not InRegion(1000,500,4000,800)
SilkToBoardRegionClearance [Not ((IsComment or IsDesignator) And (Hide <> 'False')) and not InRegion(1000,500,4000,800)] p1:
SilkToSilkClearance [All] p0: scope1count=1 scope1_0_kind=Board scope1_0_value=Board scope2count=1 scope2_0_kind=Board scope2_0_value=Board commentlength=0
SilkToSilkClearance SilkToSilkClearance_Pb-FreeLogo [All] p0 off: scope1count=1 scope1_0_kind=Board scope1_0_value=Board scope2count=1 scope2_0_kind=Board scope2_0_value=Board commentlength=120 // Protel DXP Scope 2 Expression Was: (HasFootprint('Pb-Free_Overlay_Medium') OR HasFootprint('Pb-Free_Overlay_Small'))
SilkToSilkClearance SilkToSilkClearance_Pb-FreeLogo [(HasFootprint('Pb-Free_Overlay_Medium') OR HasFootprint('Pb-Free_Overlay_Small')) vs (HasFootprint('Pb-Free_Overlay_Medium') OR HasFootprint('Pb-Free_Overlay_Small'))] p1: silktosilkclearance=0
SilkToSilkClearance [All] p2: silktosilkclearance=3.94
SilkToSolderMaskClearance SilkToComponentPadClearance_LTST [All] p0: scope1count=1 scope1_0_kind=Footprint scope1_0_value=LTST* scope2count=1 scope2_0_kind=Board scope2_0_value=Board commentlength=0
SilkToSolderMaskClearance SilkToComponentPadClearance_1008 [All] p0 off: scope1count=1 scope1_0_kind=Footprint scope1_0_value=1008 scope2count=1 scope2_0_kind=Board scope2_0_value=Board commentlength=68 // Protel DXP Scope 2 Expression Was: (IsPad or IsFill or IsRegion)
SilkToSolderMaskClearance SilkToComponentPadClearance [All] p0 off: scope1count=1 scope1_0_kind=Board scope1_0_value=Board scope2count=1 scope2_0_kind=Board scope2_0_value=Board commentlength=87 // Protel DXP Scope 1 Expression Was: (IsPad or IsFill or IsRegion) and InAnycomponent
SilkToSolderMaskClearance "Silk to Solder Mask Opening" [All] p0: scope1count=1 scope1_0_kind=Board scope1_0_value=Board scope2count=1 scope2_0_kind=Board scope2_0_value=Board commentlength=0
SilkToSolderMaskClearance SilkToComponentPadClearance_DSF0006A [All] p0 off: scope1count=1 scope1_0_kind=Board scope1_0_value=Board scope2count=1 scope2_0_kind=Board scope2_0_value=Board commentlength=68 // Protel DXP Scope 2 Expression Was: (IsPad or IsFill or IsRegion)
SilkToSolderMaskClearance SilkToComponentPadClearance_LTST [HasFootprint('LTST*')] p1: minsilkscreentomaskgap=3.5 clearancetoexposedcopper=TRUE
SilkToSolderMaskClearance SilkToComponentPadClearance_DSF0006A [HasFootprint('DSF0006A') or HasFootprint('LTST-C170TBKT_Blue') vs (IsPad or IsFill or IsRegion)] p2: minsilkscreentomaskgap=3.5 clearancetoexposedcopper=TRUE
SilkToSolderMaskClearance SilkToComponentPadClearance_1008 [HasFootprint('1008') vs (IsPad or IsFill or IsRegion)] p3: minsilkscreentomaskgap=2.2 clearancetoexposedcopper=TRUE
SilkToSolderMaskClearance SilkToComponentPadClearance [(IsPad or IsFill or IsRegion) and InAnycomponent] p4: minsilkscreentomaskgap=5 clearancetoexposedcopper=TRUE
SilkToSolderMaskClearance "Silk to Solder Mask Opening" [All] p5: minsilkscreentomaskgap=3.94 clearancetoexposedcopper=FALSE
SolderMaskExpansion [All] p0: scope1count=1 scope1_0_kind=Board scope1_0_value=Board scope2count=1 scope2_0_kind=Board scope2_0_value=Board commentlength=0 expansion=1.97
SolderMaskExpansion [All] p1: expansion=1.97 istentingtop=FALSE
UnRoutedNet [All] p0: scope1count=1 scope1_0_kind=Board scope1_0_value=Board scope2count=1 scope2_0_kind=Board scope2_0_value=Board commentlength=0
UnRoutedNet [All] p1: checkbadconnections=TRUE
UnpouredPolygon [All] p0: scope1count=1 scope1_0_kind=Board scope1_0_value=Board scope2count=1 scope2_0_kind=Board scope2_0_value=Board commentlength=0
Width [All] p0: scope1count=1 scope1_0_kind=Board scope1_0_value=Board scope2count=1 scope2_0_kind=Board scope2_0_value=Board commentlength=0 maxlimit=100 minlimit=6 preferedwidth=10
Width [All] p1: maxlimit=100 minlimit=6 preferedwidth=10 checkconnectedcopper=TRUE
12 further rules are at their usual default settings.

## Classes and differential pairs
component class Shunt: SH-J1 SH-J2 SH-J3 SH-J4 SH-J5 SH-J6 SH-J7 SH-J8 SH-J9 SH-J10
component class Header: J3 J8 J9 J10 J11 J15 J16 J19 J22 J23 J26 J27 J28 J29 J31
component class "GND Thermals Full Flood": C33 C35 C38 C58 C59 C60 U2
component class "GND Thermals 0.75mm": C8 C9 C23 C32
component class "GND Thermals 0.5mm": J30 L8
component class "GND Full Flood": C2 C3 C4 C5 C6 C7 C11 C12 C15 C17 C19 C22 C29 C30 C31 C61 J13 J20 U7
component class AMPS262A_USB: C44 C45 C46 C47 C48 C49 C50 C51 C52 C53 C54 C55 C56 C57 C58 C59 C60 C61 C62 C63 C64 C65 C66 C67 C68 C69 C70 C71 C72 C73 C74 C75 C76 C77 C78 C79 C80 C81 C82 C83 C84 C85 C86 C87 C88 C89 C90 C91 C92 D2 J22 J23 J24 J25 L6 L7 L8 R34 R35 R36 R37 R38 R39 R40 R41 R42 R43 R44 R45 R46 R47 R48 R49 R50 R51 R52 R53 R54 R55 R56 R57 R58 R59 TP13 TP14 TP19 TP20 U4 U5 U6 U7 U8 U9 U10 U11 Y1
component class AMPS262A_TAS5830_IO: C1 C2 C3 C4 C5 C6 C7 C8 C9 C10 C11 C12 C13 C14 C15 C16 C17 C18 C19 C20 C21 C22 H1 J1 J2 J3 J4 J5 J6 J7 J8 J9 J10 J11 L1 L2 L3 L4 R1 R2 R3 R4 R5 R6 R7 R8 R9 R10 R11 S1 TP1 TP2 TP3 TP4 TP21 TP22 TP23 TP24 U1
component class AMPS262A_SPDIF_I2S_PSIA: C93 C94 C95 C96 C97 C98 C99 C100 C101 C102 C103 C104 C105 C106 C107 C108 C109 C110 C111 C112 C113 C114 C115 C116 C117 C118 C119 C120 D3 J26 J27 J28 J29 J30 J31 R60 R61 R62 R63 R64 R65 R66 R67 R68 R69 R70 R71 R72 R73 R74 R75 R76 R77 R78 R79 R80 S2 TP15 TP16 TP17 TP18 U12 U13 U14 U15 U16 U17 U18 U19 U20 U21 Y2
component class AMPS262A_PowerSupplies: C23 C24 C25 C26 C27 C28 C29 C30 C31 C32 C33 C34 C35 C36 C37 C38 C39 C40 C41 C42 C43 D1 J12 J13 J14 J15 J16 J17 J18 J19 J20 J21 L5 Q1 R12 R13 R14 R15 R16 R17 R18 R19 R20 R21 R22 R23 R24 R25 R26 R27 R28 R29 R30 R31 R32 R33 TP5 TP6 TP7 TP8 TP9 TP10 TP11 TP12 U2 U3
component class Hardware: H2 H3 H4 H5 H6 H7 H8 H9
component class Logo: Logo2
component class AMPS262A_Hardware: FID1 FID2 FID3 FID4 FID5 FID6 H2 H3 H4 H5 H6 H7 H8 H9 Logo1 Logo2 Logo3 Logo4 SH-J1 SH-J2 SH-J3 SH-J4 SH-J5 SH-J6 SH-J7 SH-J8 SH-J9 SH-J10 ZZ1 ZZ2 ZZ3
component class FiducialMark: FID1 FID2 FID3 FID4 FID5 FID6
component class AssemblyNote: ZZ1 ZZ2 ZZ3

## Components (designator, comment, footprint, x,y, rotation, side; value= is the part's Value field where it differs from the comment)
C1 "CGA4J3X7R1H684M125AB" FP-CGA4J3X7R1H684M125AB_0805-MFG 4900,756.02 r270 top
C2 "C2012X5R1V106K085AC" 0805L 3488.08,2100.24 r180 bottom
C3 "" 0805L 3487.54,2021.2 r180 bottom
C4 "CGA2B3X7R1H104K050BB" 0402L 3490.98,1961.07 r0 bottom
C5 "CGA2B3X7R1H104K050BB" 0402L 3490.98,1519.19 r0 bottom
C6 "" 0805L 3487.54,1459.05 r180 bottom
C7 "C2012X5R1V106K085AC" 0805L 3488.08,1380.02 r180 bottom
C8 "+" SM_RADIAL_10BMM 3163.94,2108.19 r180 bottom
C9 "+" SM_RADIAL_10BMM 3163.94,1372.07 r180 bottom
C10 "CGA4J3X7R1H684M125AB" FP-CGA4J3X7R1H684M125AB_0805-MFG 4900,873.52 r90 top
C11 "Capacitor" 0603L 2895.72,1475 r0 top
C12 "Capacitor" 0603L 2895.72,1535 r180 top
C13 "CGA4J3X7R1H684M125AB" FP-CGA4J3X7R1H684M125AB_0805-MFG 4905,2723.52 r90 top
C14 "C1608X7R1H474K080AC" 0603 3651.25,1527.5 r270 top
C15 "CL10B105MO8NNWC" 0603L 2895.72,1605 r180 top
C16 "C1608X7R1H474K080AC" 0603 3651.28,1678.86 r270 top
C17 "CL10B105MO8NNWC" 0603L 2899.66,1910 r180 top
C18 "C1608X7R1H474K080AC" 0603 3650,1952.5 r90 top
C19 "CL10B105MO8NNWC" 0603L 2899.66,1855.24 r180 top
C20 "C1608X7R1H474K080AC" 0603 3651.28,1801.39 r90 top
C21 "CGA4J3X7R1H684M125AB" FP-CGA4J3X7R1H684M125AB_0805-MFG 4905,2608.52 r270 top
C22 "Capacitor" 0603L 2490.5,397.94 r270 top
C23 "+" SM_RADIAL_10BMM 1983.79,4229.51 r0 bottom
C24 "GRM188R61E106KA73D" 0603L 1670.17,4226.28 r180 bottom
C25 "GRM188R61E106KA73D" 0603L 1670.17,4177.07 r180 bottom
C26 "GRM188R61E106KA73D" 0603L 1670.17,4127.86 r180 bottom
C27 "CGA2B3X7R1E104K050BB" 0402L 1675.09,4088.49 r180 bottom
C28 "CGA3E2X7R1H104K080AA" 0603L 2336.31,3625.65 r180 top
C29 "CGA6P3X7R1H475K250AB" 1210_280 2486.31,3925.65 r0 top
C30 "CGA6P3X7R1H475K250AB" 1210_280 2486.31,3625.65 r0 top
C31 "CGA6P3X7R1H475K250AB" 1210_280 2486.31,3775.65 r0 top
C32 "+" HXB_JA0 2451.31,3745.65 r0 bottom
C33 "GCM188R71C105MA64D" 0603L 2519.11,4345.09 r270 top
C34 "GCM188R71H103KA37D" 0603L 2574.11,4345.65 r90 top
C35 "DNP" 0603L 2486.31,4513.09 r270 top
C36 "C0603C101F5GACTU" 0603L 2732.53,4126.83 r270 top
C37 "CGA3E3X7R1H224K080AB" 0603L 2698.08,4520.53 r270 top
C38 "CGA3E2C0G1H221J080AA" 0603L 2781.75,4294.16 r90 top
C39 "C0603C223K4RACTU" 0603L 2830.96,4240.02 r270 top
C40 "CGA2B2C0G1H221J050BA" 0402 3571.5,4437.61 r0 top
C41 "CGA2B2C0G1H221J050BA" 0402 3569.5,4237.61 r0 top
C42 "885012205037" 0402L 236.22,2071.85 r90 top
C43 "Capacitor" 0603L 442.91,2086.61 r270 top
C44 "885012205037" 0402L 1146.65,1284.45 r90 top
C45 "885012205037" 0402L 1023.62,1284.45 r90 top
C46 "885012205037" 0402L 944.88,1284.45 r90 top
C47 "885012205037" 0402L 787.4,1284.45 r90 top
C48 "885012205037" 0402L 693.9,1505.91 r0 top
C49 "885012205037" 0402L 693.9,1471.46 r0 top
C50 "885012205037" 0402L 693.9,1628.94 r0 top
C51 "885012205037" 0402L 772.64,1865.16 r270 top
C52 "885012205037" 0402L 944.88,1865.16 r270 top
C53 "885012205037" 0402L 1023.62,1865.16 r270 top
C54 "885012205037" 0402L 1166.34,1865.16 r270 top
C55 "885012205037" 0402L 1274.61,1678.15 r180 top
C56 "885012205037" 0402L 1274.61,1614.17 r180 top
C57 "885012205037" 0402L 1875,939.96 r90 bottom
C58 "C1608X5R1A226M080AC" 0603L 1579.72,994.09 r270 bottom
C59 "C1608X5R1A226M080AC" 0603L 1343.5,984.25 r270 bottom
C60 "C1608X5R1A226M080AC" 0603L 1294.29,984.25 r270 bottom
C61 "885012205037" 0402L 1294.29,1077.76 r90 bottom
C62 "C1608X5R1A106M080AC" 0603L 1624.02,1791.34 r180 bottom
C63 "GRM152R60J105ME15D" 0402L 1604.33,1633.86 r270 bottom
C64 "885012205031" 0402L 1712.6,1574.8 r0 bottom
C65 "885012205037" 0402L 1072.83,1284.45 r90 top
C66 "885012205037" 0402L 984.25,1284.45 r90 top
C67 "885012205037" 0402L 866.14,1284.45 r90 top
C68 "885012205037" 0402L 693.9,1377.95 r0 top
C69 "885012205037" 0402L 693.9,1432.09 r0 top
C70 "885012205037" 0402L 693.9,1579.72 r0 top
C71 "885012205037" 0402L 693.9,1692.91 r0 top
C72 "885012205037" 0402L 693.9,1756.89 r0 top
C73 "885012205037" 0402L 866.14,1865.16 r270 top
C74 "885012205037" 0402L 984.25,1865.16 r270 top
C75 "885012205037" 0402L 1087.6,1865.16 r270 top
C76 "885012205037" 0402L 1274.61,1742.13 r180 top
C77 "885012205037" 0402L 1274.61,1456.69 r180 top
C78 "885012205037" 0402L 1274.61,1363.19 r180 top
C79 "885012205037" 0402L 1338.58,2755.91 r0 bottom
C80 "885012205037" 0402L 1417.32,2755.91 r180 bottom
C81 "885012205037" 0402L 467.52,2726.38 r90 bottom
C82 "885012205037" 0402L 1348.43,1722.44 r270 bottom
C83 "885012205037" 0402L 546.26,1505.91 r180 bottom
C84 "GRM1555C1H471JA01D" 0402L 344.49,728.35 r90 bottom
C85 "885012205037" 0402L 1466.54,1304.13 r180 bottom
C86 "885012205037" 0402L 265.75,733.27 r0 bottom
C87 "Capacitor" 0603L 236.38,1658.46 r270 top
C88 "885012205037" 0402L 1141.73,2047.24 r180 bottom
C89 "885012205037" 0402L 1417.32,1366.14 r0 bottom
C90 "885012205037" 0402L 1712.6,1491.14 r0 bottom
C91 "885012205037" 0402L 1496.06,1366.14 r180 bottom
C92 "885012205037" 0402L 1633.86,1491.14 r0 bottom
C93 "885012205037" 0402L 344.49,2440.94 r270 bottom
C94 "885012205037" 0402L 344.49,2834.65 r270 bottom
C95 "885012205037" 0402L 1289.37,2539.37 r180 top
C96 "EMK107BBJ106MA-T" 0603L 826.77,2598.43 r0 top
C97 "885012205037" 0402L 816.93,2637.8 r0 top
C98 "EMK107BBJ106MA-T" 0603L 728.35,2933.07 r270 bottom
C99 "885012205037" 0402L 767.72,2918.31 r270 bottom
C100 "885012205037" 0402L 767.72,2834.65 r270 bottom
C101 "EMK107BBJ106MA-T" 0603L 728.35,2824.8 r270 bottom
C102 "885012005055" 0402L 826.77,2411.42 r90 top
C103 "885012005055" 0402L 836.61,2509.84 r180 top
C104 "885012205037" 0402L 408.46,3011.81 r270 bottom
C105 "GJM1555C1H270JB01" 0402L 979.33,2805.12 r0 top
C106 "GJM1555C1H270JB01" 0402L 1058.07,2716.54 r90 top
C107 "885012005055" 0402L 738.19,2411.42 r90 top
C108 "EEE-FC1C100R" SM_RADIAL_B 492.13,3503.94 r180 bottom
C109 "EEE-FC1C100R" SM_RADIAL_B 492.13,3188.98 r180 bottom
C110 "EMK107BBJ106MA-T" 0603L 1003.94,2962.6 r90 top
C111 "885012205037" 0402L 959.65,2947.83 r90 top
C112 "CC0402KRX7R8BB472" 0402L 959.65,2874.02 r270 top
C113 "CGA2B3X7R1H683K050BB" 0402L 1018.7,2854.33 r180 top
C114 "885012205037" 0402L 1338.58,2047.24 r0 bottom
C115 "885012205037" 0402L 748.03,2047.24 r0 bottom
C116 "885012205037" 0402L 944.88,2047.24 r0 bottom
C117 "885012205037" 0402L 526.57,767.72 r270 bottom
C118 "885012205037" 0402L 1594.49,2273.62 r180 bottom
C119 "885012205037" 0402L 1373.03,2539.37 r0 top
C120 "885012205037" 0402L 1673.23,984.25 r270 bottom
D1 "PMEG060V100EPDZ" SOT1289 2241.16,3905.65 r90 top
D2 "USB RDY" LTST-C170TBKT_Blue 1033.46,885.83 r0 top
D3 "S/PDIF LOCK" LTST-C170TBKT_Blue 565.94,2559.06 r0 top
FID1 "DNP" Fiducial6.4-20 4951.22,4575.51 r0 top
FID2 "DNP" Fiducial6.4-20 347.64,97.64 r0 top
FID3 "DNP" Fiducial6.4-20 4968.72,97.64 r0 top
FID4 "DNP" Fiducial6.4-20 4951.22,4575.51 r180 bottom
FID5 "DNP" Fiducial6.4-20 4968.72,97.64 r180 bottom
FID6 "DNP" Fiducial6.4-20 347.64,97.64 r180 bottom
H1 "ATS-TI1OP-519-C1-R3" HSINK_ATS078036036-TI1OP-519-C1-R3 3301.36,1740.13 r90 top
H2 "M3x8mm" "APM_RM3X8MM 2701" 5161.22,4651.02 r0 top
H3 "M3x8mm" "APM_RM3X8MM 2701" 147.64,147.64 r0 top
H4 "M3x8mm" "APM_RM3X8MM 2701" 5163.72,147.64 r0 top
H5 "M3x8mm" "APM_RM3X8MM 2701" 147.64,4650.51 r0 top
H6 "M3x12mm" Keystone_24434 147.64,147.64 r180 bottom
H7 "M3x12mm" Keystone_24434 5166.22,4651.02 r180 bottom
H8 "M3x12mm" Keystone_24434 5168.72,147.64 r180 bottom
H9 "M3x12mm" Keystone_24434 147.64,4655.51 r180 bottom
J1 "DNP" HARWIN_S1911-46R 4230,811.02 r270 top
J2 "Left" JST_B2PS-VH 5030,807.95 r0 top
J3 "DVDD1" Sullins_PBC02SAAN 2052.69,1267.97 r90 top
J4 "GVDD" CONN_1040 2047.86,1837.54 r0 top
J5 "AVDD" CONN_1040 2191.86,1837.54 r0 top
J6 "Right" JST_B2PS-VH 5025.38,2671.02 r0 top
J7 "DNP" HARWIN_S1911-46R 4205,2670.16 r90 top
J8 "ADR/HW" PBC03SAAN 2082.31,1499.37 r90 top
J9 "PD_DET-PDN" Sullins_PBC02SAAN 2106.62,2036.56 r270 top
J10 "SDA/HW_SEL0" PBC03SAAN 1980.41,960.95 r270 top
J11 "SCL/HW_SEL1" PBC03SAAN 2127.41,957.95 r270 top
J12 "Battery" Keystone_7006 1393.01,4562.74 r0 top locked
J13 "GND" Keystone_7007 715,4560 r0 top locked
J14 "DNP" HARWIN_S1911-46R 2916.44,3430 r0 bottom
J15 "Ext_BST" Sullins_PBC02SAAN 3290,4461.95 r0 top
J16 "BST_Bypass" Sullins_PBC02SAAN 3750,4152.5 r90 top
J17 "PVDD" Keystone_7006 3615,3760 r0 top
J18 "PVDD_EXT" HARWIN_S1911-46R 3022.5,3529.09 r270 top
J19 "5V" Sullins_PBC02SAAN 332.5,1922.5 r90 top
J20 "GND" Keystone_7007 4350,3754.71 r0 top
J21 "3.3V" CONN_1040 932.99,3354.88 r0 top
J22 "SCL" PBC03SAAN 1413,272 r270 top
J23 "SDA" PBC03SAAN 1195,275 r270 top
J24 "JTAG" SULLINS_LPPB061NGCN-RC 0,984.25 r90 bottom
J25 "USB" Molex_0475890001 10,1574.8 r270 top
J26 "IOVDD SEL" PBC03SAAN 1870.08,1525.59 r90 top
J27 "SCLK" PBC03SAAN 1771.65,2559.06 r0 top
J28 "LRCLK" PBC03SAAN 1771.65,2755.91 r0 top
J29 "SDIN" PBC03SAAN 1771.65,2362.2 r0 top
J30 "ANA IN" Switchcraft_35RASM 236.22,3346.46 r90 top locked
J31 "GPIO1 SEL" PBC03SAAN 1427.17,1968.5 r0 top
L1 "7447709100" WE-PD_1210 4580,547.36 r0 top
L2 "7447709100" WE-PD_1210 4580,1079.65 r0 top
L3 "7447709100" WE-PD_1210 4575,2933.03 r0 top
L4 "7447709100" WE-PD_1210 4575,2398.03 r0 top
L5 "XAL1010-682MEB" XAL1010 1826.31,3964.75 r90 top
L6 "LQM2HPN2R2MG0L" 1008 1382.87,1092.52 r180 bottom
L7 "MPZ2012S601AT000" MPZ2012 344.49,1668.31 r90 top
L8 "MPZ2012S601AT000" MPZ2012 88.58,1353.35 r0 bottom
Logo1 "CE Mark" CE_Mark_5mm 969,3989 r0 top
Logo2 "Texas Instruments" TI_Stacked_Overlay_Small 4377.5,4649 r0 top
Logo3 "FCC disclaimer" FCC_disclaimer_stacked 4415.63,4216.43 r0 top
Logo4 "WEEE logo" WEEE_Minimum 515,4036 r0 top
Q1 "IPC50N04S5L5R5ATMA1" PG-TDSON-8-33 2231.31,4147.31 r180 top
R1 "RC0603JR-070RL" 0603L 2233.15,1375 r270 top
R2 "Resistor" 0402L 3251.5,1637.15 r0 bottom
R3 "Resistor" 0402L 3251.5,1676.15 r0 bottom
R4 "Resistor" 0402L 3251.5,1715.15 r0 bottom
R5 "Resistor" 0402L 3249.5,1855.29 r0 bottom
R6 "RC0603JR-070RL" 0603L 2230,1625.59 r270 top
R7 "Resistor" 0402L 2535.5,445.18 r90 top
R8 "RC0603JR-072K2L" 0603 1757.98,1068.5 r90 top
R9 "RC0603JR-072K2L" 0603 1812.49,1068.5 r90 top
R10 "RC0603JR-071KL" 0603 1758,816.03 r90 top
R11 "RC0603JR-071KL" 0603 1812.47,816.03 r90 top
R12 "RCL12250000Z0EG" 2512_WIDE_VISHAY 1826.31,3894.86 r270 bottom
R13 "RC0603FR-0721KL" 0603 2568.16,4605.65 r180 top
R14 "RMCF0603ZT0R00" 0603L 2599.66,4520.53 r270 top
R15 "RC0603JR-070RL" 0603L 2629.19,4249.86 r270 top
R16 "RC0603FR-0724K9L" 0603L 2568.16,4665.65 r0 top
R17 "RC0603JR-070RL" 0603L 2732.53,4240.02 r270 top
R18 "RC0603FR-07100RL" 0603L 2781.75,4126.83 r270 top
R19 "RC0603FR-0721KL" 0603 2541.31,4509.16 r90 top
R20 "CRCW060349K9FKEA" 0603L 2648.87,4520.53 r90 top
R21 "ERJ-MS4SF4M0U" ERJMS4S 2551.31,4110.65 r180 top
R22 "RC0603JR-070RL" 0603L 3086.32,4211.65 r270 top
R23 "RC0603FR-0768KL" 0603 3085,4340 r270 top
R24 "CRCW060311K3FKEA" 0603L 2830.96,4126.83 r90 top
R25 "RC0603JR-070RL" 0603L 2970,4450 r0 top
R26 "RC0603JR-070RL" 0603L 3550,4530 r270 top
R27 "ERJ-3EKF1002V" 0603 3549.39,4336.61 r270 top
R28 "ERJ-3EKF1002V" 0603 3549.5,4134.61 r270 top
R29 "RC0603FR-074K3L" 0603 2995,4340 r90 top
R30 "RC0603JR-070RL" 0603L 2995,4205 r90 top
R31 "RC0805JR-070RL" 0805L 344.49,1791.34 r90 top
R32 "RC0603FR-07249KL" 0603L 359.25,2052.17 r90 top
R33 "RC0805JR-070RL" 0805L 935.04,3248.03 r90 bottom
R34 "RC0603FR-0766K5L" 0603L 1476.38,885.83 r180 bottom
R35 "RC0603FR-07100KL" 0603L 1579.72,885.83 r180 bottom
R36 "Resistor" 0402L 821.85,1186.02 r90 bottom
R37 "Resistor" 0402L 1683.07,720.55 r0 bottom
R38 "Resistor" 0402L 1564.96,720.55 r180 bottom
R39 "Resistor" 0402L 1875,1033.46 r90 bottom
R40 "Resistor" 0603L 1279.95,1787.6 r0 top
R41 "Resistor" 0402L 605.32,1673.23 r270 bottom
R42 "Resistor" 0201L 590.55,1870.08 r90 top
R43 "Resistor" 0201L 757.87,1943.9 r90 bottom
R44 "Resistor" 0201L 1205.71,1943.9 r0 bottom
R45 "RC0603FR-07680RL" 0603L 935.04,915.35 r90 top
R46 "Resistor" 0402L 566.93,1444.88 r270 bottom
R47 "Resistor" 0201L 1181.1,1200.79 r270 bottom
R48 "ERJ-1GN0R00C" 0201L 1397.64,1481.3 r0 bottom
R49 "ERJ2RKF43R2X" 0402L 585.63,1609.25 r0 bottom
R50 "Resistor" 0201 393.7,659.45 r90 top
R51 "Resistor" 0201 1446.85,1505.91 r180 bottom
R52 "Resistor" 0201L 1131.89,787.4 r180 bottom
R53 "Resistor" 0201 1131.89,836.61 r0 bottom
R54 "Resistor" 0201 236.22,816.93 r0 bottom
R55 "Resistor" 0201 442.91,836.61 r180 bottom
R56 "Resistor" 0201 1338.58,1358.27 r90 bottom
R57 "Resistor" 0201 1461.61,1259.84 r180 bottom
R58 "Resistor" 0201 236.22,846.46 r180 bottom
R59 "Resistor" 0402L 566.93,1370.08 r90 bottom
R60 "Resistor" 0402L 826.77,2411.42 r270 bottom
R61 "ERJ-2RKF33R0X" 0402L 1427.17,2509.84 r0 top
R62 "ERJ-2RKF33R0X" 0402L 1427.17,2460.63 r0 top
R63 "ERJ-2RKF33R0X" 0402L 1427.17,2411.42 r0 top
R64 "RMCF0603ZT0R00" 0603L 1525.59,2071.85 r270 bottom
R65 "Resistor" 0402L 836.61,2509.84 r0 bottom
R66 "Resistor" 0402L 757.87,2613.19 r270 top
R67 "Resistor" 0402L 664.37,2367.13 r270 bottom
R68 "CRCW06031K50JNEA" 0603L 492.13,2637.8 r270 bottom
R69 "CRCW0402200KJNED" 0402L 344.49,3248.03 r270 bottom
R70 "CRCW0402200KJNED" 0402L 344.49,3444.88 r90 bottom
R71 "CRCW0402680RJNED" 0402L 1018.7,2893.7 r0 top
R72 "Resistor" 0201 1574.8,2214.57 r270 bottom
R73 "RC0603JR-070RL" 0603L 1181.1,2854.33 r180 bottom
R74 "RC0603JR-070RL" 0603L 1279.53,2952.76 r90 bottom
R75 "RC0603JR-070RL" 0603L 1279.53,2706.69 r270 top
R76 "RC0603JR-070RL" 0603L 1387.8,3044.29 r90 bottom
R77 "RC0603JR-070RL" 0603L 1525.59,3051.18 r0 bottom
R78 "RC0603JR-070RL" 0603L 1525.59,2952.76 r0 bottom
R79 "Resistor" 0402L 1240.16,2805.12 r180 bottom
R80 "RC0603JR-070RL" 0603L 1525.59,2864.17 r0 bottom
S1 "PDN" SW_200USP1T1A1M2 2336.29,426.08 r0 top
S2 "I2S SEL" SW_200USP1T1A1M2 1180,3150 r270 top
SH-J1 "SNT-100-BK-G" SNT-100-BK-G 1377.5,1965 r180 top
SH-J2 "SNT-100-BK-G" SNT-100-BK-G 1870,1574.8 r90 top
SH-J3 "SNT-100-BK-G" SNT-100-BK-G 2082.31,1553.2 r90 top
SH-J4 "SNT-100-BK-G" SNT-100-BK-G 2052.5,1267.5 r0 top
SH-J5 "SNT-100-BK-G" SNT-100-BK-G 3240,4515 r0 top
SH-J6 "SNT-100-BK-G" SNT-100-BK-G 1726.3,2360 r180 top
SH-J7 "SNT-100-BK-G" SNT-100-BK-G 1725,2558.9 r180 top
SH-J8 "SNT-100-BK-G" SNT-100-BK-G 1722.5,2754.33 r180 top
SH-J9 "SNT-100-BK-G" SNT-100-BK-G 1192.5,322.5 r90 top
SH-J10 "SNT-100-BK-G" SNT-100-BK-G 1412.5,320 r90 top
TP1 "GPIO0_FAULTz" Keystone5003 2457.11,897.5 r90 top
TP2 "GPIO1_Hybrid_Pro" Keystone5003 2457.11,1133.9 r90 top
TP3 "GPIO2_PD_DET" Keystone5003 2034.2,2212.5 r90 top
TP4 "PDN" Keystone5003 2164.2,2211.5 r90 top
TP5 "VOUT" Keystone5003 2357.5,3381.95 r90 top
TP6 "VIN" Keystone5003 1884.34,4560 r90 top
TP7 "FB" Keystone5003 3290,4276.95 r0 top
TP8 "GND" Keystone5003 3800,4315 r0 top
TP9 "GND" Keystone5006 705,3635 r0 top
TP10 "GND" Keystone5006 205,430 r0 top
TP11 "GND" Keystone5006 2055,290 r0 top
TP12 "GND" Keystone5006 5000.38,1808.59 r0 top
TP13 "SCL_XMOS" Keystone5003 600.39,450 r0 top
TP14 "SDA_XMOS" Keystone5003 600.39,250 r0 top
TP15 "MCLK" TP_SM_1MM 679.13,3085.63 r90 top
TP16 "SCLK" Keystone5003 2135.5,2591.24 r0 top
TP17 "LRCLK" Keystone5003 2135.5,2787.67 r0 top
TP18 "SDIN" Keystone5003 2135.5,2394.81 r0 top
TP19 "SCL_AMP" Keystone5003 1413,550 r90 top
TP20 "SDA_AMP" Keystone5003 1195,545 r90 top
TP21 "BST_A+" Keystone5003 4262.5,1558.52 r270 top
TP22 "BST_A-" Keystone5003 4260,1693.52 r90 top
TP23 "BST_B+" Keystone5003 4260,1961.02 r90 top
TP24 "BST_B-" Keystone5003 4260,1831.02 r90 top
U1 "TAS5830DADR" DAD0032A-MFG 3301.36,1740.13 r0 top
U2 "LM5155DSSR" DSS0012B 2668.56,4372.9 r90 top
U3 "TI-TPS7XXXXD8_A" D0008A_M 344.49,2066.93 r0 bottom locked
U4 "TLV62568DBVR" DBV0005A_N 1476.38,984.25 r0 bottom
U5 "TPS736xxDBV" DBV0005A_N 1692.91,1673.23 r270 bottom
U6 "XEF216-512-TQ128-C20A" TQFP-128 984.25,1574.8 r90 bottom locked
U7 "TCA9406DCUR" DCU0008A_N 1771.65,984.25 r0 bottom
U8 "CDCE913PWR" PW0014A_L 1673.23,1328.74 r270 bottom
U9 "SN74AVC2T244" DQM0008A 1456.69,1427.17 r0 bottom
U10 "SN74LVC2G07" DSF0006A 442.91,787.4 r0 bottom
U11 "TPS3897ADRYR" DRY0006A 295.28,787.4 r0 bottom
U12 "OPTO-OUT" FP-FCR684208T_OTJ8-MFG 108.27,2854.33 r180 top
U13 "SN74AVC4T774RSVR" RSV0016A 1328.74,2460.63 r0 top
U14 "PLR237/T10BK" FP-PLR237/T10BK_PTH_9MM70_13MM50-MFG 98.43,2362.2 r270 top
U15 "PCM9211PT" PT0048A_N 688.98,2854.33 r270 top locked
U16 "74LVC2G157DCT" DCT0008A_N 984.25,2165.35 r270 bottom locked
U17 "74LVC2G157DCT" DCT0008A_N 1181.1,2165.35 r270 bottom locked
U18 "SN74LVC1G14" DCK0005A_N 492.13,3006.89 r180 bottom
U19 "74LVC2G157DCT" DCT0008A_N 787.4,2165.35 r270 bottom locked
U20 "74LVC2G157DCT" DCU0008A_L 1673.23,2214.57 r180 bottom
U21 "TI-TCA6408A-QFN_RGT-16" RGT0016A 1377.95,2854.33 r0 bottom
Y1 "ASA-24.000MHZ-L-T" FP-ASA-24.000MHZ-L-T_SMD_2MM0_1MM6-MFG 1367.95,1279.53 r180 bottom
